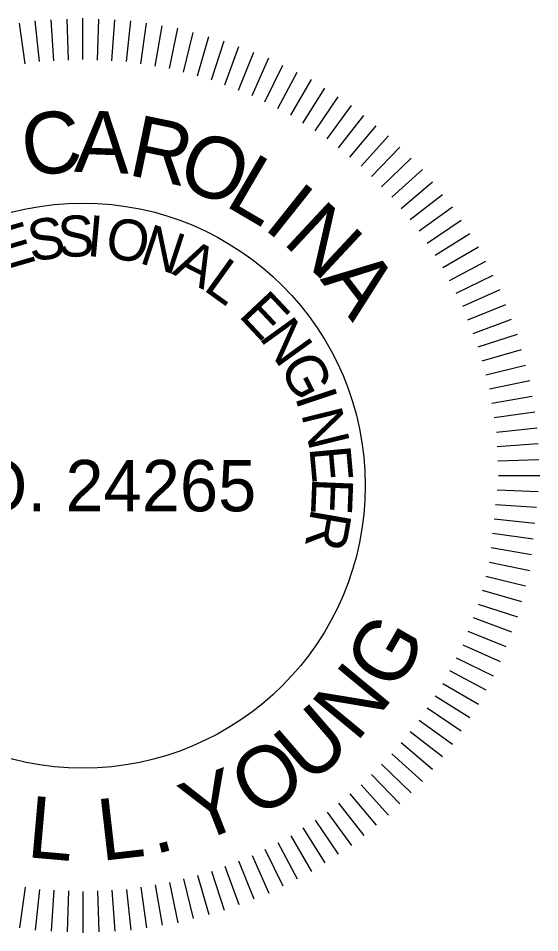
# Model space of a CAD drawing. Extents: x 1964849 to 1967422, y 1116563 to 1122211.
# Drawn here: x 1966388.6 to 1966433.8, y 1121677.6 to 1121756.8 of the extents above; entities that cross this region are included whole.
import ezdxf

# ---------------------------------------------------------------- set-up
doc = ezdxf.new("R2010")
doc.units = 0
doc.layers.add('RD_TX_PEShield', color=7, linetype='Continuous')

msp = doc.modelspace()

# ---------------------------------------------------------------- linework, layer by layer
at = {"layer": 'RD_TX_PEShield'}
for p, q in [((1966389.174, 1121752.866), (1966388.679, 1121756.387)), ((1966389.174, 1121752.866), (1966388.679, 1121756.387)), ((1966390.417, 1121753.063), (1966390.044, 1121756.604)), ((1966390.417, 1121753.063), (1966390.044, 1121756.604)), ((1966391.673, 1121753.129), (1966391.425, 1121756.676)), ((1966391.673, 1121753.129), (1966391.425, 1121756.676)), ((1966392.928, 1121753.195), (1966392.804, 1121756.748)), ((1966392.928, 1121753.195), (1966392.804, 1121756.748)), ((1966394.184, 1121753.261), (1966394.184, 1121756.821)), ((1966394.184, 1121753.261), (1966394.184, 1121756.821)), ((1966395.441, 1121753.195), (1966395.565, 1121756.748)), ((1966395.441, 1121753.195), (1966395.565, 1121756.748)), ((1966396.696, 1121753.129), (1966396.944, 1121756.676)), ((1966396.696, 1121753.129), (1966396.944, 1121756.676)), ((1966397.952, 1121753.063), (1966398.324, 1121756.604)), ((1966397.952, 1121753.063), (1966398.324, 1121756.604)), ((1966399.195, 1121752.866), (1966399.689, 1121756.387)), ((1966399.195, 1121752.866), (1966399.689, 1121756.387)), ((1966400.436, 1121752.67), (1966401.053, 1121756.171)), ((1966400.436, 1121752.67), (1966401.053, 1121756.171)), ((1966401.678, 1121752.473), (1966402.419, 1121755.955)), ((1966401.678, 1121752.473), (1966402.419, 1121755.955)), ((1966401.678, 1121752.473), (1966402.419, 1121755.955)), ((1966402.894, 1121752.147), (1966403.754, 1121755.597)), ((1966402.894, 1121752.147), (1966403.754, 1121755.597)), ((1966402.894, 1121752.147), (1966403.754, 1121755.597)), ((1966404.107, 1121751.822), (1966405.088, 1121755.24)), ((1966404.107, 1121751.822), (1966405.088, 1121755.24)), ((1966404.107, 1121751.822), (1966405.088, 1121755.24)), ((1966405.323, 1121751.496), (1966406.423, 1121754.882)), ((1966405.323, 1121751.496), (1966406.423, 1121754.882)), ((1966405.323, 1121751.496), (1966406.423, 1121754.882)), ((1966406.497, 1121751.045), (1966407.713, 1121754.387)), ((1966406.497, 1121751.045), (1966407.713, 1121754.387)), ((1966406.497, 1121751.045), (1966407.713, 1121754.387)), ((1966407.67, 1121750.595), (1966409.002, 1121753.892)), ((1966407.67, 1121750.595), (1966409.002, 1121753.892)), ((1966407.67, 1121750.595), (1966409.002, 1121753.892)), ((1966408.845, 1121750.144), (1966410.293, 1121753.396)), ((1966408.845, 1121750.144), (1966410.293, 1121753.396)), ((1966408.845, 1121750.144), (1966410.293, 1121753.396)), ((1966409.966, 1121749.573), (1966411.525, 1121752.769)), ((1966409.966, 1121749.573), (1966411.525, 1121752.769)), ((1966409.966, 1121749.573), (1966411.525, 1121752.769)), ((1966411.086, 1121749.003), (1966412.755, 1121752.142)), ((1966411.086, 1121749.003), (1966412.755, 1121752.142)), ((1966411.086, 1121749.003), (1966412.755, 1121752.142)), ((1966412.207, 1121748.431), (1966413.987, 1121751.514)), ((1966412.207, 1121748.431), (1966413.987, 1121751.514)), ((1966412.207, 1121748.431), (1966413.987, 1121751.514)), ((1966413.262, 1121747.746), (1966415.146, 1121750.762)), ((1966413.262, 1121747.746), (1966415.146, 1121750.762)), ((1966413.262, 1121747.746), (1966415.146, 1121750.762)), ((1966414.316, 1121747.062), (1966416.304, 1121750.01)), ((1966414.316, 1121747.062), (1966416.304, 1121750.01)), ((1966414.316, 1121747.062), (1966416.304, 1121750.01)), ((1966415.371, 1121746.377), (1966417.463, 1121749.257)), ((1966415.371, 1121746.377), (1966417.463, 1121749.257)), ((1966415.371, 1121746.377), (1966417.463, 1121749.257)), ((1966416.349, 1121745.585), (1966418.538, 1121748.387)), ((1966416.349, 1121745.585), (1966418.538, 1121748.387)), ((1966416.349, 1121745.585), (1966418.538, 1121748.387)), ((1966417.325, 1121744.794), (1966419.611, 1121747.518)), ((1966417.325, 1121744.794), (1966419.611, 1121747.518)), ((1966417.325, 1121744.794), (1966419.611, 1121747.518)), ((1966418.303, 1121744.002), (1966420.685, 1121746.648)), ((1966418.303, 1121744.002), (1966420.685, 1121746.648)), ((1966418.303, 1121744.002), (1966420.685, 1121746.648)), ((1966419.193, 1121743.113), (1966421.663, 1121745.67)), ((1966419.193, 1121743.113), (1966421.663, 1121745.67)), ((1966419.193, 1121743.113), (1966421.663, 1121745.67)), ((1966420.081, 1121742.224), (1966422.639, 1121744.694)), ((1966420.081, 1121742.224), (1966422.639, 1121744.694)), ((1966420.081, 1121742.224), (1966422.639, 1121744.694)), ((1966420.971, 1121741.334), (1966423.616, 1121743.716)), ((1966420.971, 1121741.334), (1966423.616, 1121743.716)), ((1966420.971, 1121741.334), (1966423.616, 1121743.716)), ((1966421.763, 1121740.357), (1966424.486, 1121742.642)), ((1966421.763, 1121740.357), (1966424.486, 1121742.642)), ((1966421.763, 1121740.357), (1966424.486, 1121742.642)), ((1966422.553, 1121739.38), (1966425.355, 1121741.569)), ((1966422.553, 1121739.38), (1966425.355, 1121741.569)), ((1966422.553, 1121739.38), (1966425.355, 1121741.569)), ((1966423.345, 1121738.402), (1966426.225, 1121740.495)), ((1966423.345, 1121738.402), (1966426.225, 1121740.495)), ((1966423.345, 1121738.402), (1966426.225, 1121740.495)), ((1966424.03, 1121737.347), (1966426.978, 1121739.335)), ((1966424.03, 1121737.347), (1966426.978, 1121739.335)), ((1966424.03, 1121737.347), (1966426.978, 1121739.335)), ((1966424.715, 1121736.293), (1966427.73, 1121738.177)), ((1966424.715, 1121736.293), (1966427.73, 1121738.177)), ((1966424.715, 1121736.293), (1966427.73, 1121738.177)), ((1966425.4, 1121735.238), (1966428.483, 1121737.018)), ((1966425.4, 1121735.238), (1966428.483, 1121737.018)), ((1966425.4, 1121735.238), (1966428.483, 1121737.018)), ((1966425.971, 1121734.117), (1966429.111, 1121735.786)), ((1966425.971, 1121734.117), (1966429.111, 1121735.786)), ((1966425.971, 1121734.117), (1966429.111, 1121735.786)), ((1966426.542, 1121732.997), (1966429.738, 1121734.556)), ((1966426.542, 1121732.997), (1966429.738, 1121734.556)), ((1966426.542, 1121732.997), (1966429.738, 1121734.556)), ((1966427.113, 1121731.876), (1966430.365, 1121733.324)), ((1966427.113, 1121731.876), (1966430.365, 1121733.324)), ((1966427.113, 1121731.876), (1966430.365, 1121733.324)), ((1966427.564, 1121730.702), (1966430.861, 1121732.034)), ((1966427.564, 1121730.702), (1966430.861, 1121732.034)), ((1966427.564, 1121730.702), (1966430.861, 1121732.034)), ((1966428.014, 1121729.529), (1966431.355, 1121730.745)), ((1966428.014, 1121729.529), (1966431.355, 1121730.745)), ((1966428.014, 1121729.529), (1966431.355, 1121730.745)), ((1966428.465, 1121728.354), (1966431.851, 1121729.454)), ((1966428.465, 1121728.354), (1966431.851, 1121729.454)), ((1966428.465, 1121728.354), (1966431.851, 1121729.454)), ((1966428.791, 1121727.139), (1966432.209, 1121728.119)), ((1966428.791, 1121727.139), (1966432.209, 1121728.119)), ((1966428.791, 1121727.139), (1966432.209, 1121728.119)), ((1966429.116, 1121725.925), (1966432.566, 1121726.785)), ((1966429.116, 1121725.925), (1966432.566, 1121726.785)), ((1966429.116, 1121725.925), (1966432.566, 1121726.785)), ((1966429.442, 1121724.71), (1966432.924, 1121725.45)), ((1966429.442, 1121724.71), (1966432.924, 1121725.45)), ((1966429.442, 1121724.71), (1966432.924, 1121725.45)), ((1966429.638, 1121723.467), (1966433.14, 1121724.084)), ((1966429.638, 1121723.467), (1966433.14, 1121724.084)), ((1966429.638, 1121723.467), (1966433.14, 1121724.084)), ((1966429.835, 1121722.226), (1966433.356, 1121722.721)), ((1966429.835, 1121722.226), (1966433.356, 1121722.721)), ((1966429.835, 1121722.226), (1966433.356, 1121722.721)), ((1966430.032, 1121720.983), (1966433.572, 1121721.355)), ((1966430.032, 1121720.983), (1966433.572, 1121721.355)), ((1966430.032, 1121720.983), (1966433.572, 1121721.355)), ((1966430.098, 1121719.727), (1966433.645, 1121719.975)), ((1966430.098, 1121719.727), (1966433.645, 1121719.975)), ((1966430.098, 1121719.727), (1966433.645, 1121719.975)), ((1966430.163, 1121718.472), (1966433.717, 1121718.596)), ((1966430.163, 1121718.472), (1966433.717, 1121718.596)), ((1966430.163, 1121718.472), (1966433.717, 1121718.596)), ((1966430.229, 1121717.216), (1966433.789, 1121717.216)), ((1966430.229, 1121717.216), (1966433.789, 1121717.216)), ((1966430.229, 1121717.216), (1966433.789, 1121717.216)), ((1966430.097, 1121715.961), (1966433.644, 1121715.838)), ((1966430.097, 1121715.961), (1966433.644, 1121715.838)), ((1966429.966, 1121714.713), (1966433.5, 1121714.466)), ((1966429.966, 1121714.713), (1966433.5, 1121714.466)), ((1966429.835, 1121713.468), (1966433.356, 1121713.098)), ((1966429.835, 1121713.468), (1966433.356, 1121713.098)), ((1966429.705, 1121712.223), (1966433.213, 1121711.73)), ((1966429.705, 1121712.223), (1966433.213, 1121711.73)), ((1966429.573, 1121710.975), (1966433.069, 1121710.359)), ((1966429.573, 1121710.975), (1966433.069, 1121710.359)), ((1966429.442, 1121709.721), (1966432.924, 1121708.981)), ((1966429.442, 1121709.721), (1966432.924, 1121708.981)), ((1966429.116, 1121708.506), (1966432.566, 1121707.646)), ((1966429.116, 1121708.506), (1966432.566, 1121707.646)), ((1966428.791, 1121707.292), (1966432.209, 1121706.312)), ((1966428.791, 1121707.292), (1966432.209, 1121706.312)), ((1966428.465, 1121706.077), (1966431.851, 1121704.977)), ((1966428.465, 1121706.077), (1966431.851, 1121704.977)), ((1966428.014, 1121704.902), (1966431.355, 1121703.686)), ((1966428.014, 1121704.902), (1966431.355, 1121703.686)), ((1966427.564, 1121703.729), (1966430.861, 1121702.397)), ((1966427.564, 1121703.729), (1966430.861, 1121702.397)), ((1966427.113, 1121702.555), (1966430.365, 1121701.107)), ((1966427.113, 1121702.555), (1966430.365, 1121701.107)), ((1966426.542, 1121701.434), (1966429.738, 1121699.875)), ((1966426.542, 1121701.434), (1966429.738, 1121699.875)), ((1966425.971, 1121700.314), (1966429.111, 1121698.645)), ((1966425.971, 1121700.314), (1966429.111, 1121698.645)), ((1966425.4, 1121699.193), (1966428.483, 1121697.413)), ((1966425.4, 1121699.193), (1966428.483, 1121697.413)), ((1966424.715, 1121698.138), (1966427.73, 1121696.254)), ((1966424.715, 1121698.138), (1966427.73, 1121696.254)), ((1966424.03, 1121697.084), (1966426.978, 1121695.096)), ((1966424.03, 1121697.084), (1966426.978, 1121695.096)), ((1966423.345, 1121696.029), (1966426.225, 1121693.936)), ((1966423.345, 1121696.029), (1966426.225, 1121693.936)), ((1966422.553, 1121695.051), (1966425.355, 1121692.862)), ((1966422.553, 1121695.051), (1966425.355, 1121692.862)), ((1966421.763, 1121694.074), (1966424.486, 1121691.789)), ((1966421.763, 1121694.074), (1966424.486, 1121691.789)), ((1966420.971, 1121693.097), (1966423.616, 1121690.715)), ((1966420.971, 1121693.097), (1966423.616, 1121690.715)), ((1966420.081, 1121692.207), (1966422.639, 1121689.737)), ((1966420.081, 1121692.207), (1966422.639, 1121689.737)), ((1966419.193, 1121691.319), (1966421.663, 1121688.761)), ((1966419.193, 1121691.319), (1966421.663, 1121688.761)), ((1966418.303, 1121690.429), (1966420.685, 1121687.783)), ((1966417.325, 1121689.637), (1966419.611, 1121686.913)), ((1966417.325, 1121689.637), (1966419.611, 1121686.913)), ((1966416.349, 1121688.846), (1966418.538, 1121686.044)), ((1966416.349, 1121688.846), (1966418.538, 1121686.044)), ((1966414.316, 1121687.369), (1966416.304, 1121684.421)), ((1966414.316, 1121687.369), (1966416.304, 1121684.421)), ((1966415.371, 1121688.054), (1966417.463, 1121685.174)), ((1966415.371, 1121688.054), (1966417.463, 1121685.174)), ((1966413.262, 1121686.685), (1966415.146, 1121683.669)), ((1966413.262, 1121686.685), (1966415.146, 1121683.669)), ((1966412.207, 1121686), (1966413.987, 1121682.917)), ((1966412.207, 1121686), (1966413.987, 1121682.917)), ((1966411.086, 1121685.428), (1966412.755, 1121682.289)), ((1966411.086, 1121685.428), (1966412.755, 1121682.289)), ((1966408.845, 1121684.287), (1966410.293, 1121681.035)), ((1966408.845, 1121684.287), (1966410.293, 1121681.035)), ((1966409.966, 1121684.858), (1966411.525, 1121681.662)), ((1966409.966, 1121684.858), (1966411.525, 1121681.662)), ((1966406.497, 1121683.386), (1966407.713, 1121680.044)), ((1966406.497, 1121683.386), (1966407.713, 1121680.044)), ((1966407.67, 1121683.836), (1966409.002, 1121680.539)), ((1966407.67, 1121683.836), (1966409.002, 1121680.539)), ((1966404.107, 1121682.609), (1966405.088, 1121679.191)), ((1966404.107, 1121682.609), (1966405.088, 1121679.191)), ((1966405.323, 1121682.935), (1966406.423, 1121679.549)), ((1966405.323, 1121682.935), (1966406.423, 1121679.549)), ((1966400.436, 1121681.761), (1966401.053, 1121678.26)), ((1966400.436, 1121681.761), (1966401.053, 1121678.26)), ((1966401.678, 1121681.958), (1966402.419, 1121678.476)), ((1966401.678, 1121681.958), (1966402.419, 1121678.476)), ((1966402.894, 1121682.284), (1966403.754, 1121678.834)), ((1966402.894, 1121682.284), (1966403.754, 1121678.834)), ((1966389.174, 1121681.565), (1966388.679, 1121678.044)), ((1966389.174, 1121681.565), (1966388.679, 1121678.044)), ((1966390.417, 1121681.368), (1966390.044, 1121677.827)), ((1966390.417, 1121681.368), (1966390.044, 1121677.827)), ((1966391.673, 1121681.302), (1966391.425, 1121677.755)), ((1966391.673, 1121681.302), (1966391.425, 1121677.755)), ((1966392.928, 1121681.236), (1966392.804, 1121677.683)), ((1966392.928, 1121681.236), (1966392.804, 1121677.683)), ((1966394.184, 1121681.171), (1966394.184, 1121677.611)), ((1966394.184, 1121681.171), (1966394.184, 1121677.611)), ((1966395.441, 1121681.236), (1966395.565, 1121677.683)), ((1966395.441, 1121681.236), (1966395.565, 1121677.683)), ((1966396.696, 1121681.302), (1966396.944, 1121677.755)), ((1966396.696, 1121681.302), (1966396.944, 1121677.755)), ((1966397.952, 1121681.368), (1966398.324, 1121677.827)), ((1966397.952, 1121681.368), (1966398.324, 1121677.827)), ((1966399.195, 1121681.565), (1966399.689, 1121678.044)), ((1966399.195, 1121681.565), (1966399.689, 1121678.044))]:
    msp.add_line(p, q, dxfattribs=at)
msp.add_circle((1966394.184, 1121716.337), 24.475, dxfattribs=at)

# ---------------------------------------------------------------- texts
for s, height, rotation, p in [('C', 5.34, 6.88322, (1966389.178, 1121743.075)), ('A', 5.34, 357.94482, (1966393.393, 1121743.528)), ('R', 5.34, 348.26699, (1966397.976, 1121743.274)), ('O', 5.34, 339.32858, (1966402.115, 1121742.358)), ('L', 5.34, 329.65075, (1966406.376, 1121740.655)), ('I', 5.34, 321.46627, (1966409.714, 1121738.671)), ('N', 5.34, 317.00069, (1966411.406, 1121737.394)), ('S', 3.56, 8.69092, (1966389.672, 1121735.725)), ('S', 3.56, 1.78995, (1966392.034, 1121736.127)), ('I', 3.56, 354.88899, (1966394.428, 1121736.242)), ('E', 3.56, 16.18428, (1966387.182, 1121734.971)), ('O', 3.56, 350.40454, (1966395.983, 1121736.162)), ('N', 3.56, 341.70291, (1966398.962, 1121735.662)), ('A', 3.56, 333.00129, (1966401.83, 1121734.716)), ('L', 3.56, 324.29966, (1966404.523, 1121733.348)), ('A', 5.34, 307.32286, (1966414.7, 1121734.199)), ('E', 3.56, 313.22511, (1966407.598, 1121731.045)), ('N', 3.56, 305.73175, (1966409.401, 1121729.17)), ('G', 3.56, 297.03012, (1966411.168, 1121726.721)), ('I', 3.56, 288.3285, (1966412.543, 1121724.032)), ('N', 3.56, 283.84405, (1966413.089, 1121722.573)), ('E', 3.56, 275.14243, (1966413.814, 1121719.641)), ('E', 3.56, 267.64906, (1966414.077, 1121717.053)), ('R', 3.56, 260.15569, (1966414.001, 1121714.452)), ('G', 5.34, 60.11131, (1966421.293, 1121698.314)), ('N', 5.34, 50.43348, (1966417.878, 1121694.013)), ('U', 5.34, 40.75564, (1966413.788, 1121690.348)), ('O', 5.34, 31.07781, (1966409.14, 1121687.422)), ('Y', 5.34, 21.39998, (1966404.066, 1121685.32)), ('L', 5.34, 354.98347, (1966389.234, 1121684.162)), ('L', 5.34, 6.51713, (1966395.768, 1121683.822)), ('.', 5.34, 14.70161, (1966400.38, 1121684.379))]:
    msp.add_text(s, height=height, rotation=rotation, dxfattribs=at).set_placement(p)
msp.add_text('NO. 24265', height=4.4501, dxfattribs=at).set_placement((1966380.43, 1121714.112))

doc.saveas('drawing.dxf')
